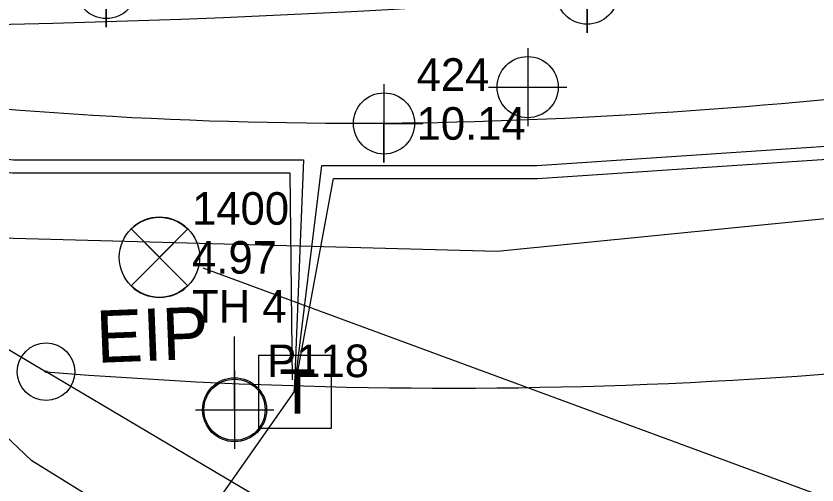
# Model space of a CAD drawing. Extents: x 2597630 to 2605918, y 617194 to 635093.
# Drawn here: x 2605269.8 to 2605331.2, y 618416.2 to 618452.2 of the extents above; entities that cross this region are included whole.
import ezdxf

# ---------------------------------------------------------------- set-up
doc = ezdxf.new("R2010")
doc.units = 0
for name, color, linetype in [('COGO Default Chain', 7, 'Continuous'), ('COGO Default Curve', 7, 'Continuous'), ('Cogo Default Point CELL', 7, 'Continuous'), ('COGO Default Point Number', 7, 'Continuous'), ('Exist DTM Crownline Cogo Point CELL', 7, 'Continuous'), ('Exist Property Iron Pin CELL', 7, 'Continuous'), ('Exist Property Iron Pin Text', 7, 'Continuous'), ('Exist Property Line', 7, 'Continuous'), ('Exist Property Tie Line', 7, 'Continuous'), ('Exist Right of Way Line', 7, 'Continuous'), ('Exist Roads EOP', 7, 'Continuous'), ('Exist Roads EOP Cogo Elevation', 7, 'Continuous'), ('Exist Roads EOP Cogo Number', 7, 'Continuous'), ('Exist Roads EOP Cogo Point CELL', 7, 'Continuous'), ('Exist Roads Soil', 7, 'Continuous'), ('Exist Utilities Power Pole CELL', 7, 'Continuous'), ('Exist Utilities Telephone Pedestal CELL', 7, 'Continuous'), ('Exist Utilities Telephone UG Cable SUE LOS C', 7, 'Continuous'), ('Exist Utilities Water Test Hole SUE LOS A CELL', 7, 'Continuous'), ('Exist Utilities Water Test Hole SUE LOS A Cogo Comment', 7, 'Continuous'), ('Exist Utilities Water Test Hole SUE LOS A Cogo Elevation', 7, 'Continuous'), ('Exist Utilities Water Test Hole SUE LOS A Cogo Number', 7, 'Continuous'), ('Exist Utilities Water Test Hole SUE LOS A Leader', 7, 'Continuous'), ('Exist Utilities Water UG Line SUE LOS B', 7, 'Continuous')]:
    doc.layers.add(name, color=color, linetype=linetype)

# ---------------------------------------------------------------- blocks, each defined once
blk = doc.blocks.new('EXIST PROPERTY IRON PIN')
at = {"layer": 'Exist Property Iron Pin CELL'}
for radius in [0.0441, 0.00141]:
    blk.add_circle((0, 0), radius, dxfattribs=at)
blk = doc.blocks.new('COGO DEFAULT POINT')
at = {"layer": 'Cogo Default Point CELL'}
for points in [[(0, 0.06), (0, 0)], [(-0.06, 0), (0, 0)], [(0, 0), (0.06, 0)], [(0, 0), (0, -0.06)]]:
    blk.add_lwpolyline(points, dxfattribs=at)
blk.add_circle((0, 0), 0.0469, dxfattribs=at)
blk = doc.blocks.new('EXIST DTM CROWNLINE COGO POINT')
at = {"layer": 'Exist DTM Crownline Cogo Point CELL'}
blk.add_lwpolyline([(0, 0.06), (0, -0.06), (0, 0), (0.06, 0), (-0.06, 0)], dxfattribs=at)
blk.add_circle((0, 0), 0.0469, dxfattribs=at)
blk = doc.blocks.new('EXIST ROADS EOP COGO POINT')
at = {"layer": 'Exist Roads EOP Cogo Point CELL'}
blk.add_lwpolyline([(0, 0.06), (0, -0.06), (0, 0), (0.06, 0), (-0.06, 0)], dxfattribs=at)
blk.add_circle((0, 0), 0.0469, dxfattribs=at)
blk = doc.blocks.new('EXIST UTILITIES WATER TEST HOLE SUE LOS A')
at = {"layer": 'Exist Utilities Water Test Hole SUE LOS A CELL'}
for points in [[(0.0435, 0.0435), (-0.0435, -0.0435), (0, 0), (-0.0435, 0.0435), (0.0435, -0.0435)], [(-0.0435, 0.0435), (0, 0), (0.0435, 0.0435)], [(0.0435, -0.0435), (0, 0), (-0.0435, -0.0435)]]:
    blk.add_lwpolyline(points, dxfattribs=at)
blk.add_circle((0, 0), 0.0615, dxfattribs=at)
for start, end in [(45, 135), (225, 315)]:
    blk.add_arc((0, 0), 0.0615, start, end, dxfattribs=at)

msp = doc.modelspace()

# ---------------------------------------------------------------- linework, layer by layer
at = {"layer": 'COGO Default Chain'}
msp.add_arc((2605251.285, 619284.353), 833, 266.740256, 281.141578, dxfattribs=at)
at = {"layer": 'COGO Default Curve'}
msp.add_arc((2605251.285, 619284.353), 833, 266.740256, 281.141578, dxfattribs=at)
at = {"layer": 'Cogo Default Point CELL'}
for points in [[(2605308.99, 618449.717), (2605308.99, 618446.717)], [(2605305.99, 618446.717), (2605308.99, 618446.717)], [(2605308.99, 618446.717), (2605311.99, 618446.717)], [(2605308.99, 618446.717), (2605308.99, 618443.717)]]:
    msp.add_lwpolyline(points, dxfattribs=at)
msp.add_circle((2605308.99, 618446.717), 2.344, dxfattribs=at)
at = {"layer": 'Exist Property Line'}
msp.add_line((2605542.201, 618264.748), (2605272.082, 618424.888), dxfattribs=at)
at = {"layer": 'Exist Property Tie Line'}
msp.add_line((2605226.836, 618451.712), (2605272.082, 618424.888), dxfattribs=at)
at = {"layer": 'Exist Right of Way Line'}
msp.add_arc((2605303.057, 618806.002), 382.371, 265.35348, 281.14158, dxfattribs=at)
at = {"layer": 'Exist Roads EOP'}
msp.add_spline([(2605554.931, 618488.691), (2605518.323, 618479.552), (2605476.771, 618470.314), (2605429.068, 618460.66), (2605388.393, 618453.139), (2605342.247, 618446.788), (2605297.978, 618443.933), (2605250.493, 618446.948), (2605224.746, 618451.291), (2605188.067, 618461.914), (2605143.175, 618481.98), (2605101.821, 618506.05), (2605057.725, 618535.842), (2605018.828, 618564.087), (2604984.62, 618589.304), (2604956.97, 618610.183)], degree=3, dxfattribs=at)
at = {"layer": 'Exist Roads Soil'}
msp.add_lwpolyline([(2605410.26, 618342.113), (2605382.108, 618356.279), (2605349.436, 618372.951), (2605321.802, 618387.554), (2605294.535, 618403.068), (2605280.097, 618412.053), (2605274.942, 618415.599), (2605270.995, 618418.066), (2605266.787, 618422.055), (2605262.501, 618428.094), (2605260.788, 618431.024), (2605259.862, 618435.539), (2605259.814, 618438.685), (2605260.671, 618441.94), (2605263.028, 618443.74), (2605265.401, 618444.491), (2605268.178, 618445.131)], dxfattribs=at)
at = {"layer": 'Exist Utilities Power Pole CELL'}
for q in [(2605286.526, 618427.598), (2605286.526, 618421.973)]:
    msp.add_line((2605286.526, 618421.973), q, dxfattribs=at)
msp.add_circle((2605286.526, 618421.973), 2.45, dxfattribs=at)
at = {"layer": 'Exist Utilities Telephone Pedestal CELL'}
msp.add_line((2605291.093, 618423.377), (2605291.093, 618423.377), dxfattribs=at)
msp.add_lwpolyline([(2605288.369, 618420.551), (2605293.963, 618420.551), (2605293.963, 618426.146), (2605288.369, 618426.146), (2605288.369, 618420.551)], dxfattribs=at)
at = {"layer": 'Exist Utilities Telephone UG Cable SUE LOS C'}
for points in [[(2605035.066, 618529.174), (2605044.701, 618541.284), (2605064.459, 618527.372), (2605084.583, 618513.704), (2605100.475, 618503.765), (2605114.433, 618495.379), (2605124.434, 618489.604), (2605135.591, 618483.21), (2605148.008, 618476.685), (2605160.516, 618470.334), (2605171.841, 618465.29), (2605179.513, 618461.899), (2605191.486, 618457.352), (2605197.211, 618455.484), (2605216.999, 618449.631), (2605228.628, 618446.625), (2605244.658, 618443.836), (2605269.573, 618441.133), (2605291.807, 618441.133), (2605291.093, 618423.377)], [(2605035.567, 618529.349), (2605044.896, 618539.924), (2605063.89, 618526.549), (2605084.036, 618512.866), (2605099.952, 618502.912), (2605113.925, 618494.517), (2605123.935, 618488.737), (2605135.109, 618482.333), (2605147.549, 618475.796), (2605160.086, 618469.431), (2605171.435, 618464.376), (2605179.133, 618460.973), (2605191.153, 618456.408), (2605196.914, 618454.529), (2605216.732, 618448.667), (2605228.417, 618445.647), (2605244.518, 618442.845), (2605269.519, 618440.133), (2605290.766, 618440.133), (2605290.933, 618424.271)], [(2605291.093, 618423.377), (2605293.227, 618440.701), (2605309.703, 618440.701), (2605344.457, 618443.022), (2605375.435, 618447.659), (2605410.927, 618453.517), (2605459.669, 618463.344), (2605509.596, 618474.193), (2605521.618, 618477.331)], [(2605291.265, 618424.372), (2605294.111, 618439.701), (2605309.736, 618439.701), (2605344.564, 618442.026), (2605375.591, 618446.671), (2605411.107, 618452.533), (2605459.874, 618462.365), (2605509.828, 618473.22), (2605521.87, 618476.363)], [(2605291.093, 618423.377), (2605273.604, 618398.416), (2605320.457, 618372.583), (2605375.677, 618342.683), (2605383.566, 618338.378)]]:
    msp.add_lwpolyline(points, dxfattribs=at)
at = {"layer": 'Exist Utilities Water Test Hole SUE LOS A Leader'}
msp.add_line((2605284.086, 618432.856), (2605336.696, 618413.461), dxfattribs=at)
at = {"layer": 'Exist Utilities Water UG Line SUE LOS B'}
msp.add_lwpolyline([(2604726.889, 618802.825), (2604728.623, 618800.62), (2604750.622, 618775.419), (2604790.386, 618735.469), (2604815.583, 618710.966), (2604846.421, 618684.691), (2604883.421, 618655.421), (2604920.609, 618626.25), (2604956.469, 618598.67), (2605000.193, 618568.419), (2605036.439, 618543.714), (2605076.168, 618517.089), (2605118.843, 618487.791), (2605146.777, 618472.232), (2605179.699, 618456.688), (2605215.856, 618442.587), (2605263.864, 618435.28), (2605306.639, 618434.129), (2605336.924, 618437.158), (2605382.69, 618444.237), (2605417.11, 618449.886), (2605451.772, 618457.953), (2605484.983, 618464.773), (2605522.806, 618473.788)], dxfattribs=at)

# ---------------------------------------------------------------- block references
at = {"layer": 'Cogo Default Point CELL', "xscale": 50, "yscale": 50}
msp.add_blockref('COGO DEFAULT POINT', (2605286.526, 618421.973), dxfattribs=at)
at = {"layer": 'Exist DTM Crownline Cogo Point CELL', "xscale": 50, "yscale": 50}
for p in [(2605276.698, 618454.319), (2605276.698, 618454.319), (2605313.545, 618453.887), (2605313.545, 618453.887)]:
    msp.add_blockref('EXIST DTM CROWNLINE COGO POINT', p, dxfattribs=at)
at = {"layer": 'Exist Property Iron Pin CELL', "xscale": 50, "yscale": 50}
msp.add_blockref('EXIST PROPERTY IRON PIN', (2605272.082, 618424.888), dxfattribs=at)
at = {"layer": 'Exist Roads EOP Cogo Point CELL', "xscale": 50, "yscale": 50}
msp.add_blockref('EXIST ROADS EOP COGO POINT', (2605297.978, 618443.933), dxfattribs=at)
msp.add_blockref('EXIST ROADS EOP COGO POINT', (2605297.978, 618443.933), dxfattribs=at)
at = {"layer": 'Exist Utilities Water Test Hole SUE LOS A CELL', "xscale": 50, "yscale": 50}
msp.add_blockref('EXIST UTILITIES WATER TEST HOLE SUE LOS A', (2605280.768, 618433.663), dxfattribs=at)

# ---------------------------------------------------------------- texts
at = {"layer": 'COGO Default Point Number'}
msp.add_text('P118', height=2.5, dxfattribs=at).set_placement((2605289.026, 618424.473))
at = {"layer": 'Exist Property Iron Pin Text'}
msp.add_text('EIP', height=4, rotation=2.25059, dxfattribs=at).set_placement((2605275.991, 618425.568))
at = {"layer": 'Exist Roads EOP Cogo Elevation'}
msp.add_text('10.14', height=2.5, dxfattribs=at).set_placement((2605300.478, 618442.683))
at = {"layer": 'Exist Roads EOP Cogo Number'}
msp.add_text('424', height=2.5, dxfattribs=at).set_placement((2605300.478, 618446.433))
at = {"layer": 'Exist Utilities Telephone Pedestal CELL'}
msp.add_text('T', height=3.42, dxfattribs=at).set_placement((2605289.962, 618421.664))
at = {"layer": 'Exist Utilities Water Test Hole SUE LOS A Cogo Comment'}
msp.add_text('TH 4', height=2.5, dxfattribs=at).set_placement((2605283.268, 618428.663))
at = {"layer": 'Exist Utilities Water Test Hole SUE LOS A Cogo Elevation'}
msp.add_text('4.97', height=2.5, dxfattribs=at).set_placement((2605283.268, 618432.413))
at = {"layer": 'Exist Utilities Water Test Hole SUE LOS A Cogo Number'}
msp.add_text('1400', height=2.5, dxfattribs=at).set_placement((2605283.268, 618436.163))

doc.saveas('drawing.dxf')
